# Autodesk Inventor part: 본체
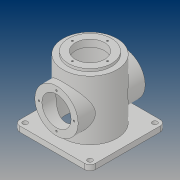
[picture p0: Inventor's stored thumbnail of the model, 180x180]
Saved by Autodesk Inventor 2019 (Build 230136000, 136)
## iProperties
Created: 2019-03
Part Number: 본체
Material: 일반
Document SubType Name: Modeling
Designer: PC312-03
Density: 1 g/cm^3
Appearance: 기본값
Author: PC312-03
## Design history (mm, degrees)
sketch "스케치1"
  geometry: C1 r 50 at (0, 0); 1 further point
  constraints: 1 centre point, 1 coincident
  dimensions: "d0" = 100 diameter of C1
extrude "돌출1" new body sketch "스케치1" distance "d1" = 120; taper "d2" = 0 deg
sketch "스케치2"
  geometry: C1 r 45 at (0, 0); 1 further point
  constraints: 1 centre point, 1 coincident
  dimensions: "d3" = 90 diameter of C1
extrude "돌출2" cut sketch "스케치2" distance "d4" = 112; taper "d5" = 0 deg
sketch "스케치3"
  geometry: L1 (-70, 70)-(70, 70); L2 (70, 70)-(70, -70); L3 (70, -70)-(-70, -70); L4 (-70, -70)-(-70, 70); L5 (-70, 70)-(70, -70); L6 (70, 70)-(-70, -70); C1 r 45 at (0, 0) reference; C2 r 50 at (0, 0) reference; 1 further point
  constraints: 12 end point, 2 midpoint, 2 parallel, 1 horizontal, 1 perpendicular
  dimensions: "d6" = 140 distance of L2.end L3.end; "d7" = 140 distance of L1.end L2.end
extrude "돌출3" join sketch "스케치3" distance "d8" = 10; taper "d9" = 0 deg
node "작업 평면1"
sketch "스케치4"
  geometry: C1 r 40 at (0, 60); 1 further point
  constraints: 1 centre point, 1 vertical alignment
  dimensions: "d11" = 80 diameter of C1; "d12" = 60 distance of point (0, 0) C1.centre
extrude "돌출4" join sketch "스케치4" stored distance "d13" = 10; taper "d14" = 0 deg
sketch "스케치5"
  geometry: C1 r 40 at (0, 0) reference; 2 further points
  constraints: 1 vertical alignment
  dimensions: "d15" = 32.5 distance of C1.centre point (0, 32.5)
hole "구멍1" sketch "스케치5" at (0, 32.5) diameter "d16" = 3.242; stored, may be unused: countersink angle "d20" = 90 deg, drill point angle "d22" = 118 deg; dims "d17" = 8, "d18" = 4, "d19" = 2, "d21" = 10
sketch "스케치6"
  geometry: C1 r 40 at (0, 0) reference; C2 r 27 at (0, 0); 1 further point
  constraints: 1 centre point, 1 coincident
  dimensions: "d26" = 54 diameter of C2
extrude "돌출5" cut sketch "스케치6" extent not by distance; stored distance "d27" = 10; taper "d28" = 0 deg
sketch "스케치7"
  geometry: C1 r 40 at (0, 0); 1 further point
  constraints: 1 centre point, 1 coincident
  dimensions: "d29" = 80 diameter of C1
extrude "돌출6" join sketch "스케치7" distance "d30" = 5; taper "d31" = 0 deg
sketch "스케치8"
  geometry: 2 further points
  constraints: 1 vertical alignment
  dimensions: "d32" = 32.5 distance of point (0, 0) point (0, 32.5)
hole "구멍2" sketch "스케치8" at (0, 32.5) diameter "d33" = 3.242; stored, may be unused: countersink angle "d37" = 90 deg, drill point angle "d39" = 118 deg; dims "d34" = 8, "d35" = 4, "d36" = 2, "d38" = 10
sketch "스케치9"
  geometry: C1 r 27 at (0, 0); 1 further point
  constraints: 1 centre point, 1 coincident
  dimensions: "d43" = 54 diameter of C1
extrude "돌출7" cut sketch "스케치9" extent not by distance; stored distance "d44" = 5; taper "d45" = 0 deg
fillet "모깎기1" dims "d46" = 10
sketch "스케치10"
  geometry: A1 r 10 centre (-60, -60) between (-70, -60) and (-60, -70) reference; A2 r 10 centre (60, -60) between (60, -70) and (70, -60) reference; A3 r 10 centre (60, 60) between (70, 60) and (60, 70) reference; A4 r 10 centre (-60, 60) between (-60, 70) and (-70, 60) reference; 5 further points
  constraints: 4 coincident
hole "구멍3" sketch "스케치10" at (-60, -60), (60, -60), (60, 60), (-60, 60) diameter "d47" = 9; stored, may be unused: countersink angle "d51" = 90 deg, drill point angle "d53" = 118 deg; dims "d48" = 8, "d49" = 4, "d50" = 2, "d52" = 10
node "솔리드1"
pattern_circular "원형 패턴1" dims angle "d24" = 360 deg
mirror "미러1"
pattern_circular "원형 패턴2" dims angle "d41" = 360 deg
node "투영된 루프1"
other parameters: "d10" = 62
